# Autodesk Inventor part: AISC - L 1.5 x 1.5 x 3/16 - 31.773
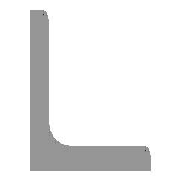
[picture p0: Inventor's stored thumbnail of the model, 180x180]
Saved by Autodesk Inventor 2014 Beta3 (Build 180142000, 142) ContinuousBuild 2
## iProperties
_CCFamilyMember: 5
_CCFamilyDisplayName: ANSI L (Equal angles) - Angle Steel
_FrameMemberDoc: Frame Member File
_Version: 15.0.0
_GetPNFromCC: 1
Created: 2010-11
Part Number: AISC - L 1.5 x 1.5 x 3/16 - 31.773
Material: Steel, Mild
Description: Angle Steel
Document SubType Name: Modeling
Standard: ANSI
Designer: Beta-8540w
Standards Organization: ANSI
Language: en-US
Size Designation: L 1.5 x 1.5 x 3/16
Categories: <MemberInstance><Categories><Category DisplayName="Structural Shapes" InternalName="089c4875-fa83-4c05-b084-43b9cc11f5ed" Mnemonic="GRDR"><CategoryParameter Dis
Stock Number: L 1.5 x 1.5 x 3/16
Density: 7.86 g/cm^3
Appearance: Steel
IsCustomPart: 1
G_L: 31.773 in
G_W: 1.500 in
G_H: 1.500 in
+D492D07F-02B9-496C-B776-82EB711B3C50+CUTDETAIL1: Cut
Author: Beta-8540w
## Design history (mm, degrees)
node "Start plane"
node "End plane"
sketch "Sketch"
  geometry: L1 (38.1, 0)-(0, 0); L2 (0, 0)-(0, 38.1); L3 (0, 38.1)-(2.476, 38.1); L4 (4.762, 35.814)-(4.762, 9.589); L5 (9.588, 4.763)-(35.814, 4.763); L6 (38.1, 2.477)-(38.1, 0); L7 (0, -11.041)-(0, 31.538); L8 (-11.041, 0)-(31.538, 0); L9 (0, 48.496)-(0, -20.964) reference; L10 (-20.964, 0)-(48.496, 0) reference; A1 r 4.826 centre (9.588, 9.589) between (4.762, 9.589) and (9.588, 4.763); A2 r 2.286 centre (2.476, 35.814) between (4.762, 35.814) and (2.476, 38.1); A3 r 2.286 centre (35.814, 2.477) between (38.1, 2.477) and (35.814, 4.763); 3 further points
  constraints: 16 end point, 6 point on circle, 6 point on line, 6 tangent, 4 parallel, 3 centre point, 2 collinear, 1 equal radius, 1 horizontal, 1 perpendicular
  dimensions: "d0" = 38.1 distance between parallel lines of L6 L2 (= G_H); "d1" = 38.1 distance between parallel lines of L3 L1 (= G_H); "d2" = 4.7625 distance between parallel lines of L2 L4 (= G_T); "d3" = 4.7625 distance between parallel lines of L1 L5 (= G_T); "d10" = 0 distance between parallel lines of L7 L2 (computed from ex); "d11" = 0 distance between parallel lines of L8 L1 (computed from d10); "d14" = 4.826 radius of A1 (= G_IR); "d15" = 2.286 radius of A2 (= G_ER)
extrude "Body" new body sketch "Sketch" stored distance "d4" = 807.0404 (= G_L); taper "d5" = 0 deg
node "Driven Length"
  sketch "Sketch3"
    geometry: L1 (0, 0)-(10, 0) reference
    constraints: 2 end point, 1 horizontal
  workplane "Work Plane3"
  sketch "Sketch4"
    geometry: L1 (-2, 0)-(12, 0) reference; L2 (-2, 807.04)-(12, 807.04) reference
    dimensions: "d17" = 807.0404 distance between parallel lines of L1 L2 (derived)
workplane "Work Plane4"
split "Split1"
body "Solid1"
other parameters: "G_H" = 38.1 [user parameter; used in 2 equation terms], "G_T" = 4.7625 [user parameter; used in 2 equation terms], "G_ER" = 2.286 [user parameter; used in 1 equation term], "G_IR" = 4.826 [user parameter; used in 1 equation term], "G_L" = 807.0404 (= d17) [user parameter; used in 1 equation term], "ex" = 0 [user parameter; used in 1 equation term], "G_OFFSET_START" = 0 [user parameter; used in 1 equation term], "G_OFFSET_END" = -29.72503 [user parameter; used in 1 equation term], "d12" = 0 (computed from G_OFFSET_START), "d13" = 807.0404 (= G_OFFSET_END + B_L), "B_L" = 836.76542 [user parameter; used in 1 equation term], "d16" = 90 deg, "MAS" = 0.26787 [user parameter]
